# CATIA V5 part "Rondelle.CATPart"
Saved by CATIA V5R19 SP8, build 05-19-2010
Part number: Rondelle
Revision: ANY
Definition: UNKNOWN
Nomenclature: Rondelle
Source: Unknown
Bounding box of the stored display mesh (mm): x -5 to 5, y -4.99 to 4.99, z 0 to 1.5
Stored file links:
  D:\Documents\1_Travail\1 - ac-limoges.fr\OneDrive - ac-limoges.fr\STI2D_Turgot\2 -2I2D\3_SEQUENCE_Serre_Connectée\3- Spécificités\ITEC\EC 3 Ouverture automatique\Simulation  Ouverture Automatique\Rondelle.CATPart
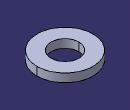
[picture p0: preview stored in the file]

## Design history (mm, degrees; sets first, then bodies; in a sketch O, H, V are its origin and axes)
Body1 "NONE" (main body)
  Solid1: solid without history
